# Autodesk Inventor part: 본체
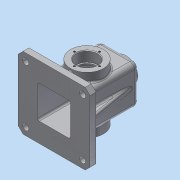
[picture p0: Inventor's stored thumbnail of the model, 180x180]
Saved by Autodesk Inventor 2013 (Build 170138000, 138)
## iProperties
Created: 2018-10
Part Number: 본체
Material: 알루미늄 6061
Document SubType Name: Modeling
Designer: Administrator
Density: 2.71 g/cm^3
Mass: 797.172 g
Surface Area: 899.5 cm^2
Volume: 294.159 cm^3
Author: Administrator
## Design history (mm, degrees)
sketch "스케치1"
  geometry: L1 (-32.5, 55)-(32.5, 55); L2 (32.5, 55)-(32.5, -55); L3 (32.5, -55)-(-32.5, -55); L4 (-32.5, -55)-(-32.5, 55); C1 r 27.5 at (0, 0); 2 further points
  constraints: 8 end point, 2 parallel, 1 centre point, 1 coincident, 1 horizontal, 1 midpoint, 1 perpendicular, 1 vertical alignment
  dimensions: "d0" = 55 diameter of C1; "d1" = 65 distance of L2.end L3.end; "d2" = 110 distance of L3.end L1.start; "d3" = 55 distance from line of L3 point (0, 0)
extrude "돌출1" new body sketch "스케치1" stored distance "d4" = 65; taper "d5" = 0 deg
sketch "스케치2"
  geometry: L1 (5, -5)-(60, -5); L2 (60, -5)-(60, -60); L3 (60, -60)-(5, -60); L4 (5, -60)-(5, -5); L5 (5, -5)-(60, -60); L6 (60, -5)-(5, -60); 1 further point
  constraints: 12 end point, 2 midpoint, 2 parallel, 1 horizontal, 1 perpendicular
  dimensions: "d6" = 55 distance of L2.end L3.end; "d7" = 55 distance of L1.end L2.end
extrude "돌출2" cut sketch "스케치2" distance "d8" = 105; taper "d9" = 0 deg
fillet "모깎기3" dims "d12" = 3
fillet "모깎기4" dims "d13" = 3
sketch "스케치5"
  geometry: L1 (65, 0)-(65, -65) reference; L2 (0, 0)-(65, 0) reference; L3 (0, 0)-(0, -65) reference; L4 (65, -65)-(0, -65) reference; L5 (-27.5, 27.5)-(92.5, 27.5); L6 (92.5, 27.5)-(92.5, -92.5); L7 (92.5, -92.5)-(-27.5, -92.5); L8 (-27.5, -92.5)-(-27.5, 27.5); L9 (-27.5, 27.5)-(92.5, -92.5); L10 (92.5, 27.5)-(-27.5, -92.5); 1 further point
  constraints: 12 end point, 2 midpoint, 2 parallel, 1 horizontal, 1 perpendicular
  dimensions: "d22" = 120 distance of L6.end L7.end; "d23" = 120 distance of L5.end L6.end
extrude "돌출4" join sketch "스케치5" distance "d24" = 10; taper "d25" = 0 deg
sketch "스케치6"
  geometry: C1 r 27.5 at (0, 0); 1 further point
  constraints: 1 centre point, 1 coincident
  dimensions: "d26" = 55 diameter of C1
extrude "돌출5" join sketch "스케치6" distance "d27" = 15; taper "d28" = 0 deg
hole "구멍1" diameter "d31" = 30; stored, may be unused: countersink angle "d35" = 90 deg, drill point angle "d37" = 118 deg; dims "d29" = 10, "d30" = 10, "d32" = 6, "d33" = 35, "d34" = 17, "d36" = 8
sketch "스케치7"
  geometry: C1 r 17.5 at (0, 0) reference; 1 further point
  constraints: 1 vertical alignment
  dimensions: "d38" = 21 distance of C1.centre point (0, 21)
hole "구멍2" sketch "스케치7" at (0, 21) diameter "d39" = 3.242; stored, may be unused: countersink angle "d43" = 90 deg, drill point angle "d45" = 118 deg; dims "d40" = 8, "d41" = 35, "d42" = 17, "d44" = 10
fillet "모깎기5" dims "d49" = 8
fillet "모깎기6" dims "d50" = 8
node "작업 평면1"
sketch "스케치8"
  geometry: C1 r 20 at (60, -60); 1 further point
  constraints: 1 centre point, 1 coincident
  dimensions: "d52" = 40 diameter of C1
extrude "돌출6" join sketch "스케치8" stored distance "d53" = 15; taper "d54" = 7 deg
hole "구멍3" diameter "d57" = 22.835; stored, may be unused: countersink angle "d61" = 90 deg, drill point angle "d63" = 118 deg; dims "d55" = 10, "d56" = 10, "d58" = 8, "d59" = 35, "d60" = 17, "d62" = 10
chamfer "모따기2" distance "d64" = 8; stored, may be unused: second distance "d65" = 2, angle "d66" = 45 deg
chamfer "모따기3" distance "d67" = 8; stored, may be unused: second distance "d68" = 2, angle "d69" = 45 deg
sketch "스케치9"
  geometry: L1 (-48, -45)-(-42.894, -16.04); L2 (-60, -45)-(-60, -55) reference; L3 (-52, -45)-(52, -45) reference; 1 further point
  constraints: 2 end point, 1 point on line
  dimensions: "d70" = 12 distance from line of L2 L1.start; "d73" = 10 deg angle of L2 L1
feature "리브1" sketch "스케치9" dims "d74" = 1, "d75" = 10, "d76" = 0, "d77" = 0, "d78" = 1, "d79" = 1
sketch "스케치11"
  geometry: L1 (-41, 42.5)-(-34, 42.5); L2 (47, 27.5)-(-55, 27.5) reference; 1 further point
  constraints: 2 end point, 1 horizontal
  dimensions: "d81" = 15 distance between parallel lines of L1 L2
feature "리브2" sketch "스케치11" dims "d82" = 1, "d83" = 6, "d84" = 0, "d85" = 0, "d86" = 1, "d87" = 1
fillet "모깎기7" dims "d88" = 3
fillet "모깎기8" dims "d89" = 3
fillet "모깎기9" dims "d90" = 3
fillet "모깎기10" dims "d91" = 3
fillet "모깎기11" dims "d92" = 1
fillet "모깎기12" dims "d93" = 3
fillet "모깎기13" dims "d94" = 3
chamfer "모따기4" distance "d95" = 1; stored, may be unused: second distance "d96" = 2, angle "d97" = 45 deg
sketch "스케치12"
  geometry: L1 (4.5, 107.5)-(99.5, 107.5); L2 (99.5, 107.5)-(99.5, 12.5); L3 (99.5, 12.5)-(4.5, 12.5); L4 (4.5, 12.5)-(4.5, 107.5); L5 (4.5, 107.5)-(99.5, 12.5); L6 (99.5, 107.5)-(4.5, 12.5); 5 further points
  constraints: 12 end point, 4 coincident, 2 midpoint, 2 parallel, 1 horizontal, 1 perpendicular
  dimensions: "d98" = 95 distance of L2.end L3.end; "d99" = 95 distance of L1.end L2.end
hole "구멍4" sketch "스케치12" at (4.5, 107.5), (99.5, 107.5), (99.5, 12.5), (4.5, 12.5) diameter "d100" = 10; stored, may be unused: countersink angle "d104" = 90 deg, drill point angle "d106" = 118 deg; dims "d101" = 8, "d102" = 35, "d103" = 17, "d105" = 10
fillet "모깎기14" dims "d107" = 3
chamfer "모따기5" distance "d108" = 1; stored, may be unused: second distance "d109" = 2, angle "d110" = 45 deg
sketch "스케치13"
  geometry: L1 (20, 65)-(-20, 65) reference; L2 (-32.5, 47)-(-32.5, -44) reference; 1 further point
  constraints: 1 other
  dimensions: "d111" = 26 distance from line of point (0, 39) L1; "d112" = 32.5 distance from line of L2 point (0, 39)
feature "엠보싱1" sketch "스케치13" dims "d0" = 55, "d113" = 0.5, "d114" = 0
fillet "모깎기15" dims "d115" = 0.3
node "솔리드1"
pattern_circular "원형 패턴1" dims angle "d47" = 360 deg
mirror "대칭1"
mirror "대칭2"
mirror "대칭3"
